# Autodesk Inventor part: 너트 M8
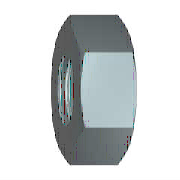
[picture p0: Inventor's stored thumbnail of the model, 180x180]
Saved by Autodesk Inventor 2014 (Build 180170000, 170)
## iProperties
IsCustomPart: 1
Created: 2012-02
Part Number: 너트 M8
Material: 강철, 연강
Description: 6각 너트 및 6각 가는 너트
Document SubType Name: Modeling
Standard: KS B 1012
Designer: mduedu
Standards Organization: KS
Language: ko-KR
Size Designation: M 8
Categories: <MemberInstance><Categories><Category DisplayName="조임쇠" InternalName="e4da775c-781d-43d5-af7c-5136215cf5a6" Mnemonic="FSTN"><Category DisplayName="너트" InternalN
Density: 7.86 g/cm^3
Mass: 4.30432 g
Surface Area: 5.27675 cm^2
Volume: 0.547623 cm^3
Appearance: 강철
Author: mduedu
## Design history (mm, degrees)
sketch "스케치1"
  geometry: L1 (-7.506, 0)-(-3.753, 6.5); L2 (-3.753, 6.5)-(3.753, 6.5); L3 (3.753, 6.5)-(7.506, 0); L4 (7.506, 0)-(3.753, -6.5); L5 (3.753, -6.5)-(-3.753, -6.5); L6 (-3.753, -6.5)-(-7.506, 0); 2 further points
  constraints: 12 end point, 1 coincident, 1 horizontal, 11 other
  dimensions: "d0" = 15.01111 distance of L3.end L1.start (= 1.1547 x SW)
extrude "본체" new body sketch "스케치1" distance "d1" = 5 (= KOH); taper "d2" = 0 deg
sketch "스케치2"
  geometry: L1 (0, 3.753)-(0, 7.506) reference; L2 (0, 7.506)-(5, 7.506) reference; L3 (5, 3.753)-(5, 7.506) reference; L4 (-1, 0)-(6, 0) reference; L5 (0.581, 7.506)-(0, 6.5); L6 (4.419, 7.506)-(5, 6.5)
  constraints: 4 end point, 4 point on line
  dimensions: "d3" = 30 deg angle of L1 L5 (= ANG1); "d4" = 30 deg angle of L3 L6 (= ANG2); "d5" = 13 diameter of L5.end L4 (= SW0); "d6" = 13 diameter of L6.end L4 (= SW01)
revolve "모따기1" sketch "스케치2" stored, may be unused: angle "d7" = 90 deg
sketch "스케치3"
  geometry: A1 r 6.5 centre (0, 0) between (-3.25, -5.629) and (3.25, -5.629) reference; 1 further point
  constraints: 1 coincident
hole "스레드" sketch "스케치3" at (0, 0) diameter "d25" = 6.647; stored, may be unused: countersink angle "d29" = 82 deg, drill point angle "d31" = 118 deg; dims "d26" = 6, "d27" = 4, "d28" = 2, "d30" = 8
workaxis "Work Axis1"
workplane "Work Plane1"
body "Solid1"
chamfer "모따기2" distance "d8" = 0.67658 (= -0.5 x GD1 + 0.5 x NND); stored, may be unused: angle "d9" = 30 deg, second distance "d40" = 0.67658 (= -0.5 x GD1 + 0.5 x NND)
chamfer "모따기3" distance "d10" = 0.67658 (= -0.5 x GD1 + 0.5 x NND); stored, may be unused: angle "d11" = 30 deg, second distance "d41" = 0.67658 (= -0.5 x GD1 + 0.5 x NND)
other parameters: "ANG1" = 30 deg [user parameter; used in 1 equation term], "ANG2" = 30 deg [user parameter; used in 1 equation term], "NND" = 8 [user parameter; used in 4 equation terms], "KOH" = 5 [user parameter; used in 1 equation term], "SW" = 13 [user parameter; used in 4 equation terms], "SW0" = 13 (= SW) [user parameter; used in 1 equation term], "SW01" = 13 (= SW) [user parameter; used in 1 equation term], "GD1" = 6.64684 (computed from THREADDIA, PTC, TOA) [user parameter; used in 4 equation terms], "d13" = 0, "d14" = 0, "d39" = 0, "d42" = 0, "GUL" = 0.67658 (= 0.541266 x PTC) [user parameter], "TPU" = 8 (computed from PTC) [user parameter], "THREADDIA" = 8 [user parameter; used in 1 equation term], "TOA" = 30 deg [user parameter; used in 1 equation term], "PTC" = 1.25 [user parameter; used in 4 equation terms], "E0" = 15.015 (= 1.155 x SW) [user parameter], "GAL" = 0.67658 (= 0.541266 x PTC) [user parameter]
